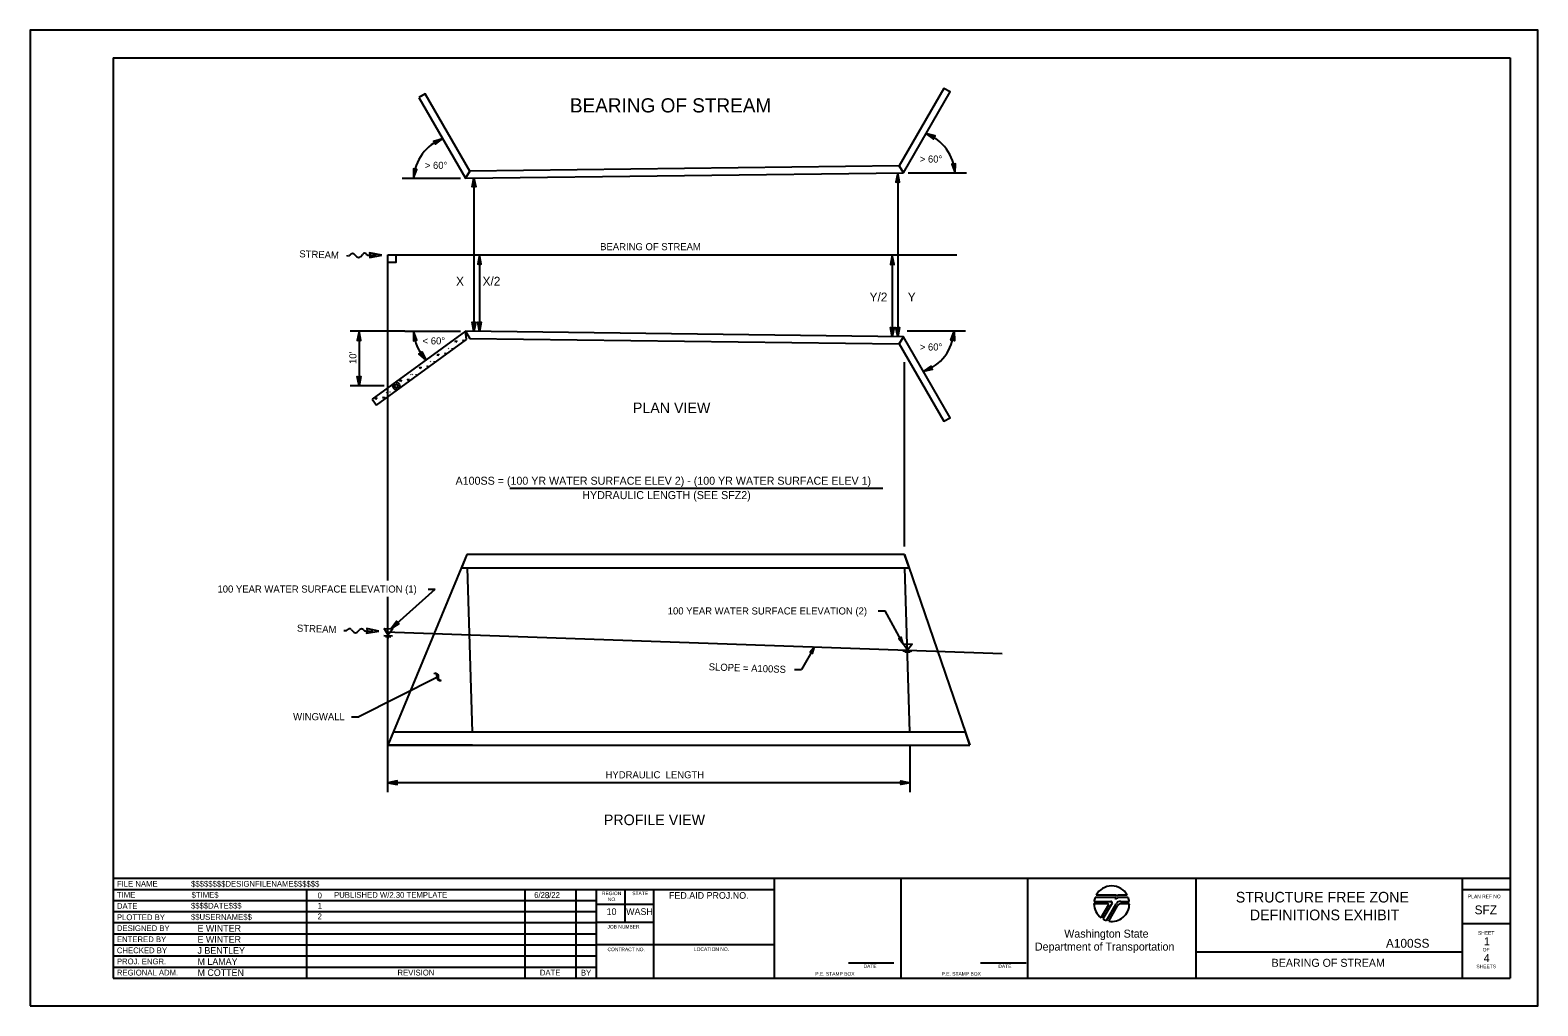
# Model space of a CAD drawing. Extents: x 99988 to 100090, y 99986 to 100024.
# Drawn here: x 99999.12 to 100016.12, y 99999.5 to 100010.5 of the extents above; entities that cross this region are included whole.
import ezdxf

# ---------------------------------------------------------------- set-up
doc = ezdxf.new("R2010")
doc.units = 0
for name, color, linetype in [('Default', 7, 'Continuous'), ('Level 15', 7, 'Continuous'), ('Level 20', 7, 'Continuous'), ('Level 22', 7, 'Continuous'), ('SH_DP_WaterSurfaceElev', 7, 'Continuous'), ('SH_GI_PlotLimits', 7, 'Continuous'), ('SH_GI_SheetBorder', 7, 'Continuous'), ('SH_GI_SheetTextInCells', 7, 'Continuous'), ('SH_GI_TitleBlockText', 7, 'Continuous'), ('SH_GI_WSDOTLogo', 7, 'Continuous'), ('TP_NT_FlowArrow', 7, 'Continuous'), ('TP_NT_Thalweg', 7, 'Continuous')]:
    doc.layers.add(name, color=color, linetype=linetype)

msp = doc.modelspace()

# ---------------------------------------------------------------- linework, layer by layer
at = {"layer": 'Default'}
for p, q in [((100003.68, 100003.248), (100003.689, 100003.253)), ((100003.698, 100003.243), (100003.68, 100003.248)), ((100003.689, 100003.253), (100003.7, 100003.251)), ((100003.705, 100003.239), (100003.698, 100003.243)), ((100003.7, 100003.251), (100003.708, 100003.248)), ((100003.71, 100003.233), (100003.705, 100003.239)), ((100003.708, 100003.248), (100003.715, 100003.243)), ((100003.712, 100003.226), (100003.71, 100003.233)), ((100003.713, 100003.214), (100003.712, 100003.226)), ((100003.715, 100003.192), (100003.713, 100003.214)), ((100003.715, 100003.243), (100003.72, 100003.237)), ((100003.72, 100003.179), (100003.715, 100003.192)), ((100003.72, 100003.237), (100003.724, 100003.225)), ((100003.724, 100003.225), (100003.726, 100003.205)), ((100003.726, 100003.205), (100003.727, 100003.192)), ((100003.727, 100003.192), (100003.73, 100003.183)), ((100003.73, 100003.183), (100003.734, 100003.178)), ((100003.725, 100003.172), (100003.72, 100003.179)), ((100003.732, 100003.167), (100003.725, 100003.172)), ((100003.74, 100003.164), (100003.732, 100003.167)), ((100003.734, 100003.178), (100003.739, 100003.174)), ((100003.739, 100003.174), (100003.748, 100003.171)), ((100003.75, 100003.163), (100003.74, 100003.164)), ((100003.748, 100003.171), (100003.759, 100003.168)), ((100003.759, 100003.168), (100003.75, 100003.163))]:
    msp.add_line(p, q, dxfattribs=at)
for radius in [0.04, 0.0196]:
    msp.add_circle((100003.254, 100006.487), radius, dxfattribs=at)
at = {"layer": 'Level 15'}
for p, q in [((100003.32, 100008.83), (100003.977, 100008.83)), ((100004.129, 100008.831), (100004.129, 100007.104)), ((100008.908, 100008.892), (100008.908, 100007.043)), ((100009.682, 100008.887), (100009.025, 100008.887)), ((100003.157, 100004.296), (100003.157, 100007.968)), ((100004.191, 100007.968), (100004.191, 100007.103)), ((100008.846, 100007.968), (100008.846, 100007.043)), ((100003.35, 100007.105), (100002.733, 100007.105)), ((100002.833, 100007.105), (100002.833, 100006.489)), ((100003.35, 100007.105), (100003.977, 100007.105)), ((100009.67, 100007.105), (100009.013, 100007.105)), ((100008.984, 100004.68), (100008.984, 100006.758)), ((100003.118, 100006.489), (100002.733, 100006.489)), ((100004.049, 100004.587), (100003.157, 100002.437)), ((100008.984, 100004.587), (100009.721, 100002.437)), ((100004.053, 100004.437), (100004.109, 100002.587)), ((100009.044, 100002.587), (100008.989, 100004.437)), ((100003.157, 100001.909), (100003.157, 100004.11)), ((100003.192, 100003.751), (100003.692, 100004.199)), ((100003.612, 100004.199), (100003.692, 100004.199)), ((100008.687, 100003.952), (100008.767, 100003.952)), ((100008.969, 100003.582), (100008.767, 100003.952)), ((100007.97, 100003.547), (100007.823, 100003.292)), ((100003.718, 100003.204), (100002.83, 100002.76)), ((100007.743, 100003.292), (100007.823, 100003.292)), ((100002.75, 100002.76), (100002.83, 100002.76)), ((100004.113, 100002.437), (100003.157, 100002.437)), ((100009.049, 100002.437), (100009.721, 100002.437)), ((100009.049, 100001.909), (100009.049, 100002.437)), ((100009.049, 100002.016), (100003.157, 100002.016))]:
    msp.add_line(p, q, dxfattribs=at)
for points in [[(100009.226, 100009.336), (100009.31, 100009.271), (100009.315, 100009.291), (100009.329, 100009.307)], [(100003.776, 100009.279), (100003.692, 100009.213), (100003.687, 100009.234), (100003.673, 100009.25)], [(100009.554, 100008.887), (100009.56, 100008.994), (100009.54, 100008.986), (100009.519, 100008.988)], [(100003.448, 100008.83), (100003.486, 100008.93), (100003.465, 100008.929), (100003.446, 100008.937)], [(100004.129, 100008.831), (100004.149, 100008.733), (100004.129, 100008.738), (100004.11, 100008.733)], [(100008.908, 100008.892), (100008.887, 100008.787), (100008.908, 100008.792), (100008.928, 100008.787)], [(100004.191, 100007.968), (100004.171, 100007.863), (100004.191, 100007.868), (100004.212, 100007.863)], [(100008.846, 100007.963), (100008.825, 100007.858), (100008.846, 100007.863), (100008.866, 100007.858)], [(100002.833, 100007.105), (100002.812, 100007), (100002.833, 100007.005), (100002.853, 100007)], [(100003.448, 100007.105), (100003.446, 100006.998), (100003.465, 100007.007), (100003.486, 100007.005)], [(100004.129, 100007.104), (100004.109, 100007.209), (100004.129, 100007.204), (100004.15, 100007.209)], [(100004.191, 100007.104), (100004.171, 100007.209), (100004.191, 100007.204), (100004.212, 100007.209)], [(100008.846, 100007.044), (100008.825, 100007.149), (100008.846, 100007.144), (100008.866, 100007.149)], [(100008.908, 100007.043), (100008.887, 100007.148), (100008.908, 100007.143), (100008.928, 100007.148)], [(100009.542, 100007.105), (100009.547, 100006.998), (100009.527, 100007.006), (100009.506, 100007.004)], [(100003.589, 100006.78), (100003.509, 100006.85), (100003.528, 100006.859), (100003.542, 100006.875)], [(100002.833, 100006.489), (100002.812, 100006.594), (100002.833, 100006.589), (100002.853, 100006.594)], [(100009.197, 100006.65), (100009.284, 100006.712), (100009.288, 100006.691), (100009.301, 100006.674)], [(100003.192, 100003.751), (100003.255, 100003.837), (100003.266, 100003.819), (100003.283, 100003.807)], [(100007.969, 100003.547), (100007.921, 100003.487), (100007.935, 100003.483), (100007.947, 100003.473)], [(100008.969, 100003.582), (100008.946, 100003.656), (100008.935, 100003.645), (100008.92, 100003.641)], [(100003.157, 100002.016), (100003.262, 100001.996), (100003.257, 100002.016), (100003.262, 100002.037)], [(100009.049, 100002.016), (100008.944, 100001.996), (100008.949, 100002.016), (100008.944, 100002.037)]]:
    msp.add_lwpolyline(points, close=True, dxfattribs=at)
msp.add_lwpolyline([(100003.249, 100007.969), (100003.249, 100007.879), (100003.159, 100007.879)], dxfattribs=at)
for centre, start, end in [((100009.045, 100008.859), 3.1008, 69.2273), ((100003.957, 100008.802), 110.7727, 176.8992), ((100003.957, 100007.133), 183.1008, 223.8104), ((100009.033, 100007.133), 288.77, 356.8992)]:
    msp.add_arc(centre, 0.509, start, end, dxfattribs=at)
at = {"layer": 'Level 20'}
msp.add_line((100004.535, 100005.335), (100008.741, 100005.335), dxfattribs=at)
at = {"layer": 'Level 22'}
for p, q in [((100008.924, 100008.972), (100004.081, 100008.911)), ((100008.971, 100008.893), (100008.924, 100008.972)), ((100004.081, 100008.911), (100004.035, 100008.83)), ((100004.035, 100008.83), (100008.971, 100008.893)), ((100004.035, 100007.105), (100002.983, 100006.338)), ((100008.971, 100007.042), (100004.035, 100007.105)), ((100004.035, 100007.105), (100004.081, 100007.024)), ((100004.045, 100007.013), (100004.035, 100007.105)), ((100003.03, 100006.273), (100004.045, 100007.013)), ((100004.039, 100007.061), (100004.04, 100007.061)), ((100004.081, 100007.024), (100008.924, 100006.963)), ((100008.924, 100006.963), (100008.971, 100007.042)), ((100003.635, 100006.767), (100003.639, 100006.763)), ((100003.681, 100006.763), (100003.68, 100006.769)), ((100003.837, 100006.914), (100003.841, 100006.91)), ((100003.883, 100006.911), (100003.882, 100006.916)), ((100003.414, 100006.62), (100003.417, 100006.616)), ((100003.433, 100006.62), (100003.437, 100006.616)), ((100003.479, 100006.616), (100003.477, 100006.622)), ((100003.139, 100006.42), (100003.142, 100006.416)), ((100003.184, 100006.417), (100003.183, 100006.422)), ((100003.231, 100006.472), (100003.235, 100006.469)), ((100003.277, 100006.469), (100003.275, 100006.474)), ((100002.983, 100006.338), (100003.03, 100006.273)), ((100004.049, 100004.587), (100003.987, 100004.437)), ((100008.984, 100004.587), (100004.049, 100004.587)), ((100009.036, 100004.437), (100008.984, 100004.587)), ((100003.987, 100004.437), (100009.036, 100004.437)), ((100003.219, 100002.587), (100003.157, 100002.437)), ((100009.67, 100002.587), (100003.219, 100002.587)), ((100009.721, 100002.437), (100009.67, 100002.587)), ((100003.157, 100002.437), (100009.721, 100002.437))]:
    msp.add_line(p, q, dxfattribs=at)
for points in [[(100008.971, 100008.893), (100009.497, 100009.804), (100009.427, 100009.844), (100008.924, 100008.972), (100008.971, 100008.893)], [(100003.509, 100009.741), (100004.035, 100008.83), (100004.081, 100008.911), (100003.579, 100009.781), (100003.509, 100009.741)], [(100004.015, 100006.991), (100004.007, 100007.005), (100004.029, 100007.001)], [(100008.924, 100006.963), (100009.427, 100006.091), (100009.497, 100006.131), (100008.971, 100007.042), (100008.924, 100006.963)], [(100003.813, 100006.844), (100003.805, 100006.858), (100003.827, 100006.854)], [(100003.611, 100006.696), (100003.603, 100006.71), (100003.625, 100006.707)], [(100003.389, 100006.549), (100003.381, 100006.563), (100003.404, 100006.56)], [(100003.114, 100006.349), (100003.106, 100006.363), (100003.128, 100006.36)]]:
    msp.add_lwpolyline(points, dxfattribs=at)
for points in [[(100003.925, 100006.977), (100003.922, 100006.992), (100003.936, 100006.992)], [(100003.723, 100006.83), (100003.72, 100006.845), (100003.734, 100006.845)], [(100003.521, 100006.683), (100003.518, 100006.698), (100003.532, 100006.698)], [(100003.3, 100006.535), (100003.297, 100006.55), (100003.311, 100006.55)], [(100003.024, 100006.336), (100003.021, 100006.351), (100003.035, 100006.351)]]:
    msp.add_lwpolyline(points, close=True, dxfattribs=at)
at = {"layer": 'SH_DP_WaterSurfaceElev'}
for p, q in [((100003.112, 100003.674), (100003.212, 100003.671)), ((100003.132, 100003.663), (100003.192, 100003.661)), ((100003.151, 100003.653), (100003.171, 100003.652)), ((100008.966, 100003.502), (100009.066, 100003.499)), ((100008.986, 100003.492), (100009.046, 100003.49)), ((100009.006, 100003.481), (100009.026, 100003.48))]:
    msp.add_line(p, q, dxfattribs=at)
for points in [[(100003.115, 100003.754), (100003.215, 100003.751), (100003.162, 100003.682)], [(100008.969, 100003.582), (100009.069, 100003.579), (100009.017, 100003.511)]]:
    msp.add_lwpolyline(points, close=True, dxfattribs=at)
at = {"layer": 'SH_GI_PlotLimits'}
msp.add_lwpolyline([(99999.125, 99999.5), (100016.125, 99999.5), (100016.125, 100010.5), (99999.125, 100010.5)], close=True, dxfattribs=at)
at = {"layer": 'SH_GI_SheetBorder'}
for p, q in [((100000.062, 100010.187), (100000.062, 99999.812)), ((100000.062, 100010.187), (100015.812, 100010.187)), ((100015.812, 100010.187), (100015.812, 99999.812)), ((100000.062, 100000.938), (100015.812, 100000.938)), ((100000.062, 100000.813), (100007.519, 100000.813)), ((100002.242, 100000.813), (100002.242, 99999.812)), ((100004.703, 100000.813), (100004.703, 99999.812)), ((100005.279, 100000.813), (100005.279, 99999.812)), ((100005.508, 100000.813), (100005.508, 99999.812)), ((100005.834, 100000.438), (100005.834, 100000.813)), ((100006.158, 99999.812), (100006.158, 100000.813)), ((100007.519, 99999.812), (100007.519, 100000.938)), ((100008.945, 99999.812), (100008.945, 100000.938)), ((100010.371, 100000.938), (100010.371, 99999.812)), ((100012.268, 100000.938), (100012.268, 99999.812)), ((100015.27, 100000.938), (100015.27, 99999.812)), ((100015.27, 100000.813), (100015.812, 100000.813)), ((100000.062, 100000.688), (100002.245, 100000.688)), ((100002.245, 100000.688), (100005.509, 100000.688)), ((100006.158, 100000.643), (100005.509, 100000.643)), ((100000.062, 100000.563), (100002.245, 100000.563)), ((100002.245, 100000.563), (100005.509, 100000.563)), ((100000.062, 100000.438), (100005.509, 100000.438)), ((100000.062, 100000.313), (100005.509, 100000.313)), ((100006.158, 100000.438), (100005.509, 100000.438)), ((100015.27, 100000.43), (100015.812, 100000.43)), ((100000.062, 100000.188), (100005.509, 100000.188)), ((100007.519, 100000.188), (100005.509, 100000.188)), ((100000.062, 100000.063), (100005.509, 100000.063)), ((100008.353, 99999.986), (100008.865, 99999.986)), ((100009.842, 99999.986), (100010.354, 99999.986)), ((100012.268, 100000.108), (100015.27, 100000.108)), ((100000.062, 99999.937), (100005.509, 99999.937)), ((100000.062, 99999.812), (100015.812, 99999.812))]:
    msp.add_line(p, q, dxfattribs=at)
at = {"layer": 'SH_GI_WSDOTLogo'}
for p, q in [((100011.12, 100000.652), (100011.277, 100000.652)), ((100011.121, 100000.678), (100011.312, 100000.678)), ((100011.352, 100000.722), (100011.132, 100000.722)), ((100011.365, 100000.748), (100011.144, 100000.748)), ((100011.284, 100000.64), (100011.199, 100000.493)), ((100011.324, 100000.659), (100011.219, 100000.48)), ((100011.261, 100000.461), (100011.371, 100000.651)), ((100011.495, 100000.748), (100011.398, 100000.748)), ((100011.507, 100000.722), (100011.405, 100000.722)), ((100011.405, 100000.722), (100011.405, 100000.722)), ((100011.418, 100000.678), (100011.518, 100000.678)), ((100011.428, 100000.652), (100011.52, 100000.652)), ((100011.287, 100000.455), (100011.387, 100000.628))]:
    msp.add_line(p, q, dxfattribs=at)
for centre, radius, start, end in [((100011.32, 100000.652), 0.2, 28.4787, 151.532), ((100011.32, 100000.652), 0.2, 179.9986, 232.8433), ((100011.32, 100000.652), 0.2, 159.696, 172.5057), ((100011.277, 100000.644), 0.0082, 329.7436, 90), ((100011.32, 100000.652), 0.2, 260.5455, 359.8086), ((100011.312, 100000.665), 0.0131, 329.7683, 90), ((100011.352, 100000.707), 0.0148, 327.8418, 89.9985), ((100011.405, 100000.673), 0.0484, 89.9953, 147.8238), ((100011.365, 100000.739), 0.00903, 329.8742, 90.0033), ((100011.418, 100000.624), 0.0542, 90, 149.9974), ((100011.398, 100000.719), 0.0287, 90.0072, 148.1676), ((100011.428, 100000.604), 0.0476, 90, 150.0543), ((100011.32, 100000.652), 0.2, 7.4943, 20.2941), ((100011.32, 100000.652), 0.2, 239.7929, 253.0448)]:
    msp.add_arc(centre, radius, start, end, dxfattribs=at)
at = {"layer": 'TP_NT_FlowArrow'}
for p, q in [((100002.697, 100007.957), (100002.716, 100007.958)), ((100002.735, 100007.966), (100002.742, 100007.973)), ((100002.78, 100007.974), (100002.81, 100007.945)), ((100002.848, 100007.946), (100002.877, 100007.975)), ((100002.915, 100007.976), (100002.922, 100007.969)), ((100002.941, 100007.962), (100003.025, 100007.963)), ((100002.663, 100003.731), (100002.682, 100003.731)), ((100002.701, 100003.738), (100002.708, 100003.745)), ((100002.746, 100003.744), (100002.775, 100003.714)), ((100002.813, 100003.714), (100002.843, 100003.742)), ((100002.881, 100003.742), (100002.888, 100003.735)), ((100002.906, 100003.727), (100002.99, 100003.725))]:
    msp.add_line(p, q, dxfattribs=at)
for points in [[(100003.089, 100007.964), (100002.953, 100007.989), (100002.96, 100007.962), (100002.954, 100007.935)], [(100003.055, 100003.724), (100002.92, 100003.753), (100002.926, 100003.726), (100002.919, 100003.7)]]:
    msp.add_lwpolyline(points, close=True, dxfattribs=at)
for centre, start, end in [((100002.716, 100007.985), 271.0224, 316.0224), ((100002.761, 100007.954), 46.0224, 136.0224), ((100002.828, 100007.964), 226.0224, 316.0224), ((100002.896, 100007.957), 46.0224, 136.0224), ((100002.94, 100007.989), 226.0224, 271.0224), ((100002.683, 100003.758), 269.0036, 314.0036), ((100002.727, 100003.725), 44.0036, 134.0036), ((100002.794, 100003.733), 224.0036, 314.0036), ((100002.862, 100003.723), 44.0036, 134.0036), ((100002.907, 100003.754), 224.0036, 269.0036)]:
    msp.add_arc(centre, 0.0269, start, end, dxfattribs=at)
at = {"layer": 'TP_NT_Thalweg'}
for p, q in [((100003.157, 100007.968), (100009.574, 100007.968)), ((100003.133, 100003.715), (100010.085, 100003.473))]:
    msp.add_line(p, q, dxfattribs=at)

# ---------------------------------------------------------------- texts
at = {"layer": 'Level 20'}
for s, height, p in [('BEARING OF STREAM', 0.16, (100005.211, 100009.572)), ('> 60°', 0.08, (100003.575, 100008.936)), ('> 60°', 0.08, (100009.156, 100009.007)), ('X', 0.1, (100003.927, 100007.619)), ('X/2', 0.1, (100004.226, 100007.619)), ('Y/2', 0.1, (100008.59, 100007.441)), ('Y', 0.1, (100009.02, 100007.441)), ('< 60°', 0.08, (100003.55, 100006.957)), ('> 60°', 0.08, (100009.156, 100006.888)), ('PLAN VIEW', 0.12, (100005.921, 100006.182)), ('A100SS = (100 YR WATER SURFACE ELEV 2) - (100 YR WATER SURFACE ELEV 1)', 0.09, (100003.922, 100005.375)), ('HYDRAULIC LENGTH (SEE SFZ2)', 0.09, (100005.351, 100005.213)), ('100 YEAR WATER SURFACE ELEVATION (1)', 0.08, (100001.237, 100004.159)), ('100 YEAR WATER SURFACE ELEVATION (2)', 0.08, (100006.314, 100003.912)), ('WINGWALL', 0.08, (100002.09, 100002.72)), ('HYDRAULIC  LENGTH', 0.08, (100005.613, 100002.065)), ('PROFILE VIEW', 0.12, (100005.594, 100001.537)), ('8', 0.07, (100004.928, 100000.714)), ('STRUCTURE FREE ZONE', 0.12, (100012.719, 100000.665)), ('DEFINITIONS EXHIBIT', 0.12, (100012.878, 100000.465))]:
    msp.add_text(s, height=height, dxfattribs=at).set_placement(p)
for s, rotation, p in [('STREAM', 357.9812, (100002.159, 100007.939)), ('BEARING OF STREAM', 360, (100005.552, 100008.019)), ("10'", 90, (100002.804, 100006.736)), ('STREAM', 357.9812, (100002.132, 100003.719)), ('SLOPE = A100SS', 358.0099, (100006.775, 100003.283))]:
    msp.add_text(s, height=0.08, rotation=rotation, dxfattribs=at).set_placement(p)
at = {"layer": 'SH_GI_SheetBorder'}
msp.add_text('PLAN REF NO', height=0.04003, dxfattribs=at).set_placement((100015.337, 100000.713))
at = {"layer": 'SH_GI_SheetTextInCells'}
for s, height, p in [('FILE NAME', 0.0651, (100000.103, 100000.843)), ('TIME', 0.0651, (100000.103, 100000.718)), ('DATE', 0.0651, (100000.103, 100000.593)), ('6/28/22', 0.0651, (100004.808, 100000.717)), ('REGION', 0.04, (100005.572, 100000.748)), ('NO.', 0.04, (100005.638, 100000.681)), ('STATE', 0.04, (100005.914, 100000.748)), ('FED.AID PROJ.NO.', 0.07506, (100006.328, 100000.707)), ('PLOTTED BY', 0.0651, (100000.103, 100000.466)), ('10', 0.0751, (100005.625, 100000.525)), ('WASH', 0.0751, (100005.845, 100000.525)), ('DESIGNED BY', 0.06505, (100000.103, 100000.343)), ('JOB NUMBER', 0.04, (100005.634, 100000.371)), ('Washington State', 0.09007, (100010.785, 100000.269)), ('SHEET', 0.04, (100015.45, 100000.302)), ('CHECKED BY', 0.0651, (100000.103, 100000.093)), ('ENTERED BY', 0.0651, (100000.103, 100000.218)), ('CONTRACT NO.', 0.04003, (100005.635, 100000.116)), ('LOCATION NO.', 0.04003, (100006.609, 100000.119)), ('Department of Transportation', 0.09007, (100010.454, 100000.123)), ('OF', 0.04, (100015.503, 100000.113)), ('PROJ. ENGR.', 0.06505, (100000.103, 99999.968)), ('DATE', 0.04, (100008.522, 99999.926)), ('DATE', 0.04, (100010.042, 99999.926)), ('SHEETS', 0.04, (100015.432, 99999.924)), ('REGIONAL ADM.', 0.06505, (100000.103, 99999.842)), ('REVISION', 0.0651, (100003.267, 99999.842)), ('DATE', 0.0651, (100004.872, 99999.842)), ('BY', 0.0651, (100005.335, 99999.841)), ('P.E. STAMP BOX', 0.04003, (100007.978, 99999.841)), ('P.E. STAMP BOX', 0.04003, (100009.402, 99999.841))]:
    msp.add_text(s, height=height, dxfattribs=at).set_placement(p)
at = {"layer": 'SH_GI_TitleBlockText'}
for s, height, p in [('$$$$$$$$DESIGNFILENAME$$$$$$', 0.06505, (100000.94, 100000.843)), ('$$$$DATE$$$', 0.06505, (100000.938, 100000.596)), ('$TIME$', 0.0651, (100000.945, 100000.718)), ('0', 0.0651, (100002.366, 100000.712)), ('1', 0.0651, (100002.366, 100000.596)), ('PUBLISHED W/2.30 TEMPLATE', 0.06505, (100002.552, 100000.718)), ('SFZ', 0.1, (100015.412, 100000.532)), ('$$USERNAME$$', 0.06505, (100000.938, 100000.469)), ('2', 0.0651, (100002.366, 100000.476)), ('E WINTER', 0.075, (100001.012, 100000.337)), ('J BENTLEY', 0.075, (100001.012, 100000.087)), ('E WINTER', 0.075, (100001.012, 100000.212)), ('A100SS', 0.1, (100014.412, 100000.155)), ('1', 0.09, (100015.518, 100000.182)), ('M LAMAY', 0.075, (100001.012, 99999.962)), ('BEARING OF STREAM ', 0.09, (100013.123, 99999.94)), ('4', 0.09, (100015.515, 99999.994)), ('M COTTEN', 0.075, (100001.012, 99999.837))]:
    msp.add_text(s, height=height, dxfattribs=at).set_placement(p)

doc.saveas('drawing.dxf')
